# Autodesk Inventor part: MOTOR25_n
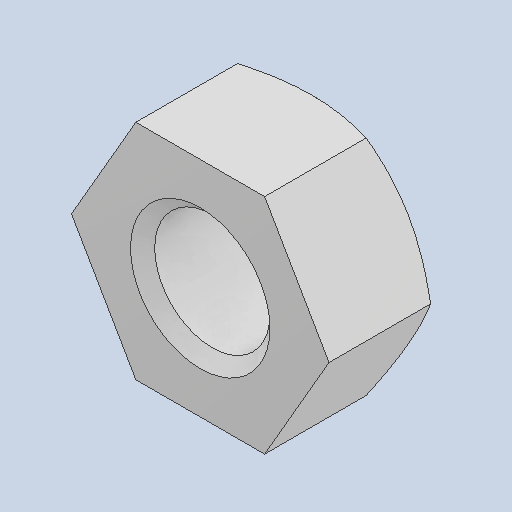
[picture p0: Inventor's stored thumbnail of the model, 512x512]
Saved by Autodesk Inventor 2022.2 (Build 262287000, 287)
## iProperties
Created: 2024-10
Part Number: MOTOR25_n
Material: Generico
Document SubType Name: Modeling
Designer: 18907419
Density: 1 g/cm^3
Appearance: Default
Author: 18907419
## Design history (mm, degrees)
feature "Solido1"
node "Solido2"
